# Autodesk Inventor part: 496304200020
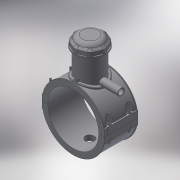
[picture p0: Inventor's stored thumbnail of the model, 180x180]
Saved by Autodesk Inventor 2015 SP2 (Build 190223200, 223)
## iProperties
Created: 2017-07
Part Number: 496304200020
Material: Generic
Description: PLASSON TAPPING SADDLE 200x20
Document SubType Name: Modeling
Designer: KIM
Mass: 1263.42 g
Surface Area: 2992.4 cm^2
Volume: 1263.42 cm^3
Density: 1 g/cm^3
Appearance: Default
Author: KIM
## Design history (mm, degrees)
derived "496304.ipt"
feature "Solid1::496304.ipt"
feature "Solid2::496304.ipt"
feature "Solid4::496304.ipt"
feature "Solid5::496304.ipt"
tag "TaggingFeature1" dims "B_" = 202
body "Solid1"
body "Solid2"
other parameters: "L_" = 176, "d_t" = 6, "H_2" = 177, "H_" = 125, "d1" = 228, "d148" = 3, "d160" = 3, "d169" = 3, "d192" = 5.6, "d2" = 262.6, "d4" = 176, "d5" = 0, "d6" = 0.1, "d8" = 0, "d19" = 6, "d20" = 6, "d21" = 105.6, "d23" = 0, "d24" = 52.8, "d26" = 0, "d29" = 3, "d30" = 66.66667, "d31" = 6, "d32" = 0, "d33" = 0, "d34" = 0.6, "d40" = 118.56, "d43" = 0, "d45" = 0, "d47" = 219.6, "d70" = 15, "d72" = 0, "d73" = 6, "d75" = 5, "d76" = 0, "d79" = 15, "d80" = 70.4, "d82" = 5 deg, "d84" = 4, "d85" = 14, "d86" = 0, "d87" = 3, "d88" = 0, "d89" = 1, "d90" = 1, "d91" = 140.8, "d92" = 0, "d93" = 0.5, "d94" = 105.26316, "d96" = 232.56, "d97" = 3.52, "d98" = 0, "d102" = 2, "d120" = 140 deg, "d121" = 24.228, "d122" = 20 deg, "d123" = 456, "d124" = 136.8, "d126" = 0, "d143" = 206, "d145" = 21.53846, "d149" = 3, "d150" = 23.69231, "d153" = 176, "d154" = 0, "d156" = 114, "d157" = 160 deg, "d159" = 5.6, "d161" = 3, "d162" = 105.6, "d163" = 0, "d168" = 111.21951, "d170" = 3, "d172" = 0, "d173" = 1, "d176" = 20 deg, "d177" = 14, "d178" = 28, "d180" = 0, "d183" = 11.2, "d184" = 11.2, "d185" = 57.2, "d186" = 57.2, "d187" = 114, "d188" = 8.4, "d189" = 14, "d190" = 0, "d191" = 171, "d193" = 5.6, "d194" = 6.16, "d195" = 90 deg, "d197" = 0, "d199" = 0, "d200" = 14, "d202" = 0, "d203" = 177, "d204" = 76, "d205" = 56, "d206" = 68, "d207" = 132.75, "d208" = 138.06, "d209" = 164.61, "d210" = 68.8, "d212" = 64, "d213" = 36, "d216" = 0, "d219" = 4, "d224" = 0, "d230" = 4, "d233" = 6, "d236" = 101, "d237" = 52.8, "d238" = 6.02433, "d240" = 52.8, "d241" = 52.8, "d242" = 52.8, "d243" = 6, "d244" = 52.8, "d245" = 52.8, "d246" = 52.8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
